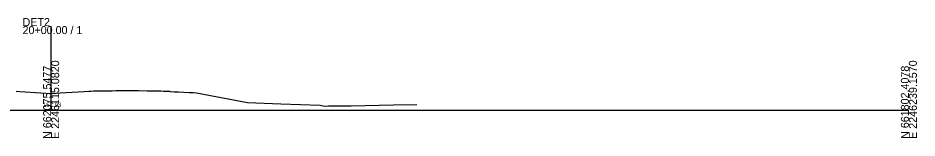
# Model space of a CAD drawing. Extents: x -26 to 603, y -10 to 9526.
# Drawn here: x 288.4 to 602.8, y 2990.3 to 3032.3 of the extents above; entities that cross this region are included whole.
import ezdxf

# ---------------------------------------------------------------- set-up
doc = ezdxf.new("R2010")
doc.units = 0
for name, color, linetype in [('Exist Cross Section Cell', 7, 'Continuous'), ('Exist XS Center Line Elevation Label', 7, 'Continuous'), ('Exist XS Ground Line', 7, 'Continuous')]:
    doc.layers.add(name, color=color, linetype=linetype)

msp = doc.modelspace()

# ---------------------------------------------------------------- linework, layer by layer
at = {"layer": 'Exist Cross Section Cell'}
for p, q in [((300, 3000), (300, 3029.47)), ((0, 3000), (300, 3000)), ((300, 3000), (600, 3000))]:
    msp.add_line(p, q, dxfattribs=at)
at = {"layer": 'Exist XS Ground Line'}
for p, q in [((287.78, 3006.65), (289.02, 3006.53)), ((289.02, 3006.53), (296.42, 3006.12)), ((296.42, 3006.12), (300, 3005.93)), ((300.3, 3005.92), (303.16, 3006.08)), ((303.16, 3006.08), (311.53, 3006.56)), ((311.53, 3006.56), (313.22, 3006.7)), ((313.22, 3006.7), (313.88, 3006.75)), ((313.88, 3006.75), (314.83, 3006.76)), ((314.83, 3006.76), (315.77, 3006.79)), ((315.77, 3006.79), (316.12, 3006.8)), ((316.12, 3006.8), (317.08, 3006.81)), ((317.08, 3006.81), (321.39, 3006.87)), ((321.39, 3006.87), (322.57, 3006.88)), ((322.57, 3006.88), (323.01, 3006.89)), ((323.01, 3006.89), (325.07, 3006.92)), ((325.07, 3006.92), (326.22, 3006.93)), ((326.22, 3006.93), (327.01, 3006.94)), ((327.01, 3006.94), (328.06, 3006.93)), ((328.06, 3006.93), (330.56, 3006.89)), ((330.56, 3006.89), (333.55, 3006.84)), ((333.55, 3006.84), (336.07, 3006.8)), ((336.07, 3006.8), (338.36, 3006.76)), ((338.36, 3006.76), (339.27, 3006.74)), ((339.27, 3006.74), (339.79, 3006.73)), ((339.79, 3006.73), (340.46, 3006.71)), ((340.46, 3006.71), (341.38, 3006.68)), ((341.38, 3006.68), (341.59, 3006.59)), ((341.59, 3006.59), (342.97, 3006.52)), ((342.97, 3006.52), (344.54, 3006.46)), ((344.54, 3006.46), (346.46, 3006.36)), ((346.46, 3006.36), (348.32, 3006.27)), ((348.32, 3006.27), (348.75, 3006.24)), ((348.75, 3006.24), (349.68, 3006.25)), ((349.68, 3006.25), (350.88, 3006.07)), ((350.88, 3006.07), (368.67, 3002.71)), ((300, 3005.93), (300.3, 3005.92)), ((368.67, 3002.71), (380.28, 3002.23)), ((380.28, 3002.23), (394.12, 3001.78)), ((394.12, 3001.78), (395.63, 3001.48)), ((395.63, 3001.48), (396.99, 3001.62)), ((396.99, 3001.62), (404.98, 3001.56)), ((404.98, 3001.56), (414.78, 3001.86)), ((414.78, 3001.86), (419.79, 3001.92)), ((419.79, 3001.92), (427.86, 3002.03))]:
    msp.add_line(p, q, dxfattribs=at)

# ---------------------------------------------------------------- texts
at = {"layer": 'Exist Cross Section Cell'}
for s, p in [('DET2', (290, 3029.47)), ('20+00.00 / 1', (290, 3026.67))]:
    msp.add_text(s, height=2.8, dxfattribs=at).set_placement(p)
for s, p in [('E 2246115.0820', (302.8, 2990)), ('E 2246239.1570', (602.8, 2990)), ('N 662075.5477', (300, 2990)), ('N 661802.4078', (600, 2990))]:
    msp.add_text(s, height=2.8, rotation=90, dxfattribs=at).set_placement(p)
at = {"layer": 'Exist XS Center Line Elevation Label'}
msp.add_text('151.93', height=1.5, dxfattribs=at).set_placement((297.17, 3001.18))

doc.saveas('drawing.dxf')
